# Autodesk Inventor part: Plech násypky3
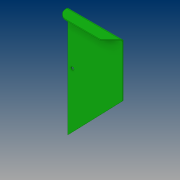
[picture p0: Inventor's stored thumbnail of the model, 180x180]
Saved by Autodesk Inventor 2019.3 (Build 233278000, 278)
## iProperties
Created: 2019-02
Part Number: Plech násypky3
Material: Ocel, měkká, svařovaná
Document SubType Name: Plech
Designer: B-hon
Density: 7.85 g/cm^3
Sheet Metal Rule: Výchozí_mm
Appearance: Tmavě zelená
Author: B-hon
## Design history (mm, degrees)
node "Plocha1"
  sketch "Náčrt1"
    geometry: L1 (114, 118.05)-(114, 229.75); L2 (114, 229.75)-(0, 229.75); L3 (0, 229.75)-(0, 0); L4 (114, 118.05)-(0, 0)
    constraints: 8 end point, 1 parallel, 1 perpendicular, 1 vertical
    dimensions: "d0" = 114 distance of L2.end L1.end; "d2" = 111.7 distance of L1.start L1.end; "d3" = 136 deg angle of L4 L1
fillet "Zaoblení1" dims "d5" = 2
node "Obruba1"
sketch "Náčrt4"
  geometry: L1 (87.004, -3.996)-(122.316, 31.316); L2 (122.316, 31.316)-(125.206, -9.442); L3 (125.206, -9.442)-(87.004, -3.996); L4 (114, 21)-(114, 0) reference; 2 further points
  constraints: 6 end point, 1 point on line
  dimensions: "d19" = 45 deg angle of L4 L1
extrude "Vysunutí1" cut sketch "Náčrt4" distance "d20" = 10; taper "d21" = 0 deg
fillet "Zaoblení2" dims "d22" = 20
sketch "Náčrt5"
  geometry: L1 (0, 0)-(0, 225.75) reference; L2 (91, 229.75)-(20, 229.75) reference; 1 further point
  dimensions: "d23" = 10 distance from line of L1 point (10, 214.75); "d24" = 15 distance from line of L2 point (10, 214.75)
hole "Díra1" sketch "Náčrt5" at (10, 214.75) diameter "d25" = 6.5; stored, may be unused: countersink angle "d29" = 90 deg, drill point angle "d31" = 118 deg; dims "d26" = 6, "d27" = 4, "d28" = 2, "d30" = 2 (= Tloušťka)
pattern_linear "Obdélníkové pole1" dims "d34" = 90
node "Těleso1"
feature "Deska1" dims "d4" = 2 (= Tloušťka)
sketch "Náčrt2"
  geometry: L1 through (-57, 0) direction (1, 0); L2 through (0, 12.5) direction (0, 1); L3 (0, 25)-(-114, 25); L4 (-114, 25)-(-114, 0)
  constraints: 6 end point, 1 horizontal, 1 perpendicular, 1 vertical
feature "Deska2" dims "d4" = 2 (= Tloušťka), "d6" = 2 (= ŠířkaVýštipu), "d7" = 1 (= HloubkaVýštipu), "d8" = 4 (= MinimálníZbytek), "d9" = 2 (= PřechodovýPoloměr), "d10" = 25, "d11" = 90 deg, "d12" = 2 (= PoloměrOhybu), "d13" = 8 (= VelikostRohovéhoVýštipu), "d14" = 2 (= VelikostMezery), "d15" = 2 (= VelikostJacobihoPoloměru), "MezeraVystřižení" = 0.01
feature "Ohyb1" dims "d4" = 2 (= Tloušťka), "d6" = 2 (= ŠířkaVýštipu), "d7" = 1 (= HloubkaVýštipu), "d8" = 4 (= MinimálníZbytek), "d9" = 2 (= PřechodovýPoloměr), "d10" = 25, "d11" = 90 deg, "d12" = 2 (= PoloměrOhybu), "MezeraVystřižení" = 0.01
feature "Roh1" dims "d10" = 25, "d11" = 90 deg, "d13" = 8 (= VelikostRohovéhoVýštipu), "d14" = 2 (= VelikostMezery), "d15" = 2 (= VelikostJacobihoPoloměru)
other parameters: "Tloušťka" = 2 (derived), "KSoučinitel" = 4.4, "PoloměrOhybu" = 2 (= Tloušťka), "ŠířkaVýštipu" = 2 (= Tloušťka), "HloubkaVýštipu" = 1 (= 0.5 x Tloušťka), "VelikostRohovéhoVýštipu" = 8 (= 4 x Tloušťka), "MinimálníZbytek" = 4 (= 2 x Tloušťka), "PřechodovýPoloměr" = 2 (= PoloměrOhybu), "VelikostJacobihoPoloměru" = 2 (= PoloměrOhybu), "VelikostMezery" = 2 (= Tloušťka)
